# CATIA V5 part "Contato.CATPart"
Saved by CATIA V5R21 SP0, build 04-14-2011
Part number: Contato
Definition: Contato
Nomenclature: Contato
Source: Unknown
Bounding box of the stored display mesh (mm): x -3.25 to 3.25, y -2.5 to 0.504, z -3.219 to 3.179
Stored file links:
  C:\Users\beatr\OneDrive\Documents\UNB\2026_1\Pi1\Componentes eletronicos\Contato.CATPart
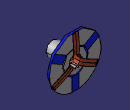
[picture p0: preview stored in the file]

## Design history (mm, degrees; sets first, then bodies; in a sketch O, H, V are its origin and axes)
Body1 "Sólido1" (main body)
  Solid1: solid without history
